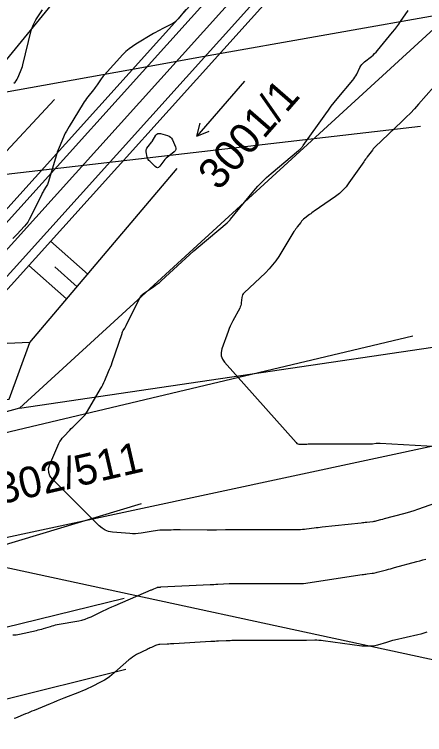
# Model space of a CAD drawing. Extents: x -534481 to -534256, y -1190577 to -1190138.
# Drawn here: x -534401.7 to -534390.37, y -1190524.99 to -1190505.1 of the extents above; entities that cross this region are included whole.
import ezdxf

# ---------------------------------------------------------------- set-up
doc = ezdxf.new("R2010")
doc.units = 0
for name, color, linetype in [('07_ELEKTRO', 7, 'Continuous'), ('30', 7, 'Continuous'), ('31', 7, 'Continuous'), ('_N_osa', 7, 'Continuous'), ('_N_text', 7, 'Continuous'), ('_tenka', 7, 'Continuous'), ('_velmi_tenka', 7, 'Continuous'), ('Hranice parcel', 7, 'Continuous'), ('Parcelní čísla', 7, 'Continuous'), ('Vnitřní kresba', 7, 'Continuous'), ('Značky kultur', 7, 'Continuous')]:
    doc.layers.add(name, color=color, linetype=linetype)

msp = doc.modelspace()

# ---------------------------------------------------------------- linework, layer by layer
at = {"layer": '07_ELEKTRO'}
msp.add_lwpolyline([(-534420.706, -1190521.11), (-534390.696, -1190513.981)], dxfattribs=at)
at = {"layer": '30'}
for points in [[(-534396.966, -1190504.966), (-534397.175, -1190505.224), (-534397.219, -1190505.273), (-534397.268, -1190505.317), (-534397.322, -1190505.355), (-534397.38, -1190505.388), (-534397.622, -1190505.506), (-534397.682, -1190505.536), (-534397.742, -1190505.567), (-534397.801, -1190505.6), (-534397.859, -1190505.634), (-534398.343, -1190505.924), (-534398.441, -1190505.987), (-534398.533, -1190506.057), (-534398.62, -1190506.133), (-534398.701, -1190506.216), (-534399.222, -1190506.783), (-534399.25, -1190506.814), (-534399.276, -1190506.846), (-534399.301, -1190506.88), (-534399.325, -1190506.914), (-534399.418, -1190507.053), (-534399.442, -1190507.088), (-534399.466, -1190507.122), (-534399.491, -1190507.155), (-534399.517, -1190507.188), (-534399.674, -1190507.383), (-534399.708, -1190507.427), (-534399.74, -1190507.472), (-534399.771, -1190507.518), (-534399.801, -1190507.565), (-534400.19, -1190508.201), (-534400.227, -1190508.262), (-534400.261, -1190508.325), (-534400.293, -1190508.388), (-534400.323, -1190508.453), (-534400.438, -1190508.714), (-534400.466, -1190508.78), (-534400.491, -1190508.846), (-534400.515, -1190508.913), (-534400.537, -1190508.981), (-534400.767, -1190509.743), (-534400.777, -1190509.772), (-534400.789, -1190509.801), (-534400.802, -1190509.829), (-534400.818, -1190509.856), (-534400.883, -1190509.963), (-534400.899, -1190509.99), (-534400.914, -1190510.017), (-534400.929, -1190510.045), (-534400.943, -1190510.073), (-534401.251, -1190510.705), (-534401.288, -1190510.773), (-534401.329, -1190510.838), (-534401.375, -1190510.899), (-534401.425, -1190510.957), (-534401.637, -1190511.183), (-534401.691, -1190511.239), (-534401.747, -1190511.292)], [(-534390.065, -1190518.606), (-534390.567, -1190518.78), (-534390.662, -1190518.811), (-534390.757, -1190518.841), (-534390.852, -1190518.869), (-534390.948, -1190518.895), (-534391.485, -1190519.038), (-534391.536, -1190519.051), (-534391.588, -1190519.065), (-534391.691, -1190519.093), (-534391.717, -1190519.099), (-534391.743, -1190519.105), (-534391.77, -1190519.11), (-534391.796, -1190519.114), (-534391.968, -1190519.135), (-534392.006, -1190519.14), (-534392.043, -1190519.144), (-534392.081, -1190519.149), (-534392.119, -1190519.153), (-534393.199, -1190519.268), (-534393.253, -1190519.274), (-534393.308, -1190519.281), (-534393.362, -1190519.287), (-534393.417, -1190519.294), (-534393.634, -1190519.323), (-534393.689, -1190519.329), (-534393.743, -1190519.334), (-534393.798, -1190519.336), (-534393.853, -1190519.337), (-534395.617, -1190519.337), (-534395.68, -1190519.337), (-534395.743, -1190519.338), (-534395.806, -1190519.339), (-534395.869, -1190519.34), (-534396.121, -1190519.345), (-534396.183, -1190519.346), (-534396.246, -1190519.347), (-534396.309, -1190519.347), (-534396.372, -1190519.347), (-534397.121, -1190519.343), (-534397.184, -1190519.342), (-534397.246, -1190519.343), (-534397.308, -1190519.343), (-534397.37, -1190519.345), (-534397.619, -1190519.35), (-534397.681, -1190519.352), (-534397.743, -1190519.357), (-534397.804, -1190519.364), (-534397.866, -1190519.374), (-534398.202, -1190519.431), (-534398.279, -1190519.441), (-534398.356, -1190519.447), (-534398.433, -1190519.447), (-534398.51, -1190519.443), (-534398.994, -1190519.399), (-534399.097, -1190519.382), (-534399.192, -1190519.347), (-534399.279, -1190519.296), (-534399.359, -1190519.229), (-534400.645, -1190517.942), (-534400.717, -1190517.85), (-534400.753, -1190517.752), (-534400.755, -1190517.646), (-534400.722, -1190517.535), (-534400.469, -1190516.954), (-534400.443, -1190516.901), (-534400.412, -1190516.85), (-534400.377, -1190516.803), (-534400.337, -1190516.758), (-534400.171, -1190516.586), (-534400.129, -1190516.543), (-534400.087, -1190516.501), (-534400.044, -1190516.459), (-534400.001, -1190516.417), (-534399.829, -1190516.25), (-534399.788, -1190516.207), (-534399.749, -1190516.162), (-534399.714, -1190516.114), (-534399.682, -1190516.063), (-534399.322, -1190515.448), (-534399.289, -1190515.39), (-534399.258, -1190515.332), (-534399.229, -1190515.272), (-534399.201, -1190515.211), (-534399.096, -1190514.967), (-534399.07, -1190514.905), (-534399.045, -1190514.844), (-534399.022, -1190514.781), (-534399, -1190514.718), (-534398.727, -1190513.914), (-534398.72, -1190513.894), (-534398.711, -1190513.875), (-534398.702, -1190513.857), (-534398.692, -1190513.838), (-534398.65, -1190513.766), (-534398.64, -1190513.748), (-534398.629, -1190513.73), (-534398.62, -1190513.711), (-534398.61, -1190513.693), (-534398.252, -1190512.965), (-534398.219, -1190512.908), (-534398.179, -1190512.856), (-534398.133, -1190512.811), (-534398.08, -1190512.771), (-534397.855, -1190512.624), (-534397.8, -1190512.586), (-534397.747, -1190512.546), (-534397.695, -1190512.504), (-534397.645, -1190512.46), (-534397.079, -1190511.936), (-534396.967, -1190511.834), (-534396.855, -1190511.733), (-534396.741, -1190511.634), (-534396.626, -1190511.536), (-534395.824, -1190510.859), (-534395.816, -1190510.852), (-534395.808, -1190510.844), (-534395.799, -1190510.836), (-534395.791, -1190510.829), (-534395.759, -1190510.797), (-534395.751, -1190510.789), (-534395.744, -1190510.78), (-534395.736, -1190510.772), (-534395.729, -1190510.763), (-534395.086, -1190509.98), (-534394.976, -1190509.851), (-534394.86, -1190509.728), (-534394.738, -1190509.61), (-534394.61, -1190509.499), (-534393.852, -1190508.864), (-534393.84, -1190508.854), (-534393.828, -1190508.844), (-534393.817, -1190508.833), (-534393.807, -1190508.822), (-534393.764, -1190508.777), (-534393.754, -1190508.765), (-534393.744, -1190508.753), (-534393.734, -1190508.741), (-534393.725, -1190508.729), (-534393.099, -1190507.849), (-534393.023, -1190507.745), (-534392.945, -1190507.642), (-534392.865, -1190507.54), (-534392.783, -1190507.44), (-534392.352, -1190506.923), (-534392.321, -1190506.883), (-534392.292, -1190506.841), (-534392.266, -1190506.798), (-534392.242, -1190506.753), (-534392.153, -1190506.57), (-534392.129, -1190506.526), (-534392.1, -1190506.486), (-534392.067, -1190506.449), (-534392.029, -1190506.416), (-534391.835, -1190506.263), (-534391.79, -1190506.226), (-534391.748, -1190506.186), (-534391.707, -1190506.145), (-534391.669, -1190506.101), (-534391.253, -1190505.595), (-534391.195, -1190505.523), (-534391.139, -1190505.45), (-534391.084, -1190505.375), (-534391.031, -1190505.3), (-534390.821, -1190504.996)], [(-534390.309, -1190522.164), (-534390.392, -1190522.192), (-534390.475, -1190522.216), (-534390.559, -1190522.237), (-534391.2, -1190522.386), (-534391.255, -1190522.399), (-534391.31, -1190522.414), (-534391.364, -1190522.429), (-534391.418, -1190522.446), (-534391.674, -1190522.526), (-534391.709, -1190522.535), (-534391.744, -1190522.542), (-534391.779, -1190522.547), (-534391.815, -1190522.549), (-534391.959, -1190522.554), (-534391.995, -1190522.555), (-534392.031, -1190522.554), (-534392.067, -1190522.551), (-534392.102, -1190522.547), (-534393.173, -1190522.403), (-534393.23, -1190522.396), (-534393.286, -1190522.392), (-534393.343, -1190522.39), (-534393.4, -1190522.39), (-534393.629, -1190522.396), (-534393.686, -1190522.397), (-534393.743, -1190522.398), (-534393.8, -1190522.398), (-534393.857, -1190522.399), (-534395.637, -1190522.399), (-534395.69, -1190522.399), (-534395.743, -1190522.4), (-534395.796, -1190522.402), (-534395.849, -1190522.404), (-534396.061, -1190522.415), (-534396.114, -1190522.418), (-534396.167, -1190522.421), (-534396.22, -1190522.424), (-534396.273, -1190522.427), (-534397.299, -1190522.484), (-534397.343, -1190522.487), (-534397.388, -1190522.489), (-534397.432, -1190522.492), (-534397.477, -1190522.494), (-534397.68, -1190522.505), (-534397.711, -1190522.508), (-534397.742, -1190522.514), (-534397.772, -1190522.522), (-534397.801, -1190522.534), (-534397.917, -1190522.586), (-534397.946, -1190522.599), (-534397.975, -1190522.613), (-534398.004, -1190522.626), (-534398.033, -1190522.641), (-534398.325, -1190522.786), (-534398.381, -1190522.817), (-534398.436, -1190522.851), (-534398.488, -1190522.889), (-534398.538, -1190522.93), (-534399.006, -1190523.342), (-534399.071, -1190523.396), (-534399.14, -1190523.445), (-534399.211, -1190523.49), (-534399.286, -1190523.53), (-534399.591, -1190523.681), (-534399.667, -1190523.718), (-534399.745, -1190523.753), (-534399.823, -1190523.786), (-534399.901, -1190523.818), (-534400.335, -1190523.989), (-534400.429, -1190524.027), (-534400.523, -1190524.065), (-534400.617, -1190524.103), (-534400.711, -1190524.142), (-534401.157, -1190524.327), (-534401.216, -1190524.351), (-534401.274, -1190524.375), (-534401.333, -1190524.399), (-534401.391, -1190524.423), (-534401.669, -1190524.536), (-534401.706, -1190524.549)]]:
    msp.add_lwpolyline(points, dxfattribs=at)
at = {"layer": '31'}
for points in [[(-534401.716, -1190507.007), (-534401.683, -1190506.973), (-534401.653, -1190506.937), (-534401.628, -1190506.897), (-534401.606, -1190506.855), (-534401.529, -1190506.679), (-534401.511, -1190506.635), (-534401.494, -1190506.59), (-534401.48, -1190506.545), (-534401.467, -1190506.499), (-534401.234, -1190505.552), (-534401.211, -1190505.474), (-534401.182, -1190505.399), (-534401.146, -1190505.326), (-534401.104, -1190505.256), (-534400.924, -1190504.982)], [(-534389.898, -1190506.863), (-534390.536, -1190507.586), (-534390.647, -1190507.708), (-534390.76, -1190507.828), (-534390.875, -1190507.945), (-534390.994, -1190508.06), (-534391.733, -1190508.758), (-534391.738, -1190508.763), (-534391.743, -1190508.768), (-534391.747, -1190508.773), (-534391.752, -1190508.778), (-534391.771, -1190508.801), (-534391.778, -1190508.809), (-534391.785, -1190508.818), (-534391.801, -1190508.84), (-534391.811, -1190508.853), (-534391.953, -1190509.04), (-534391.978, -1190509.072), (-534392.002, -1190509.105), (-534392.026, -1190509.138), (-534392.05, -1190509.172), (-534392.458, -1190509.76), (-534392.538, -1190509.865), (-534392.626, -1190509.961), (-534392.723, -1190510.05), (-534392.828, -1190510.13), (-534393.416, -1190510.538), (-534393.449, -1190510.561), (-534393.482, -1190510.585), (-534393.515, -1190510.609), (-534393.548, -1190510.634), (-534393.68, -1190510.735), (-534393.711, -1190510.76), (-534393.739, -1190510.787), (-534393.766, -1190510.816), (-534393.791, -1190510.847), (-534393.887, -1190510.973), (-534393.911, -1190511.005), (-534393.934, -1190511.038), (-534393.956, -1190511.071), (-534393.977, -1190511.104), (-534394.398, -1190511.786), (-534394.479, -1190511.907), (-534394.567, -1190512.023), (-534394.663, -1190512.133), (-534394.766, -1190512.237), (-534395.353, -1190512.792), (-534395.378, -1190512.82), (-534395.397, -1190512.85), (-534395.41, -1190512.884), (-534395.417, -1190512.92), (-534395.432, -1190513.072), (-534395.437, -1190513.11), (-534395.447, -1190513.146), (-534395.459, -1190513.181), (-534395.476, -1190513.215), (-534395.667, -1190513.568), (-534395.704, -1190513.638), (-534395.737, -1190513.71), (-534395.768, -1190513.783), (-534395.796, -1190513.858), (-534395.966, -1190514.337), (-534395.99, -1190514.439), (-534395.985, -1190514.536), (-534395.953, -1190514.627), (-534395.893, -1190514.713), (-534393.919, -1190516.93), (-534393.897, -1190516.951), (-534393.871, -1190516.965), (-534393.843, -1190516.974), (-534393.812, -1190516.975), (-534393.684, -1190516.97), (-534393.652, -1190516.969), (-534393.62, -1190516.969), (-534393.588, -1190516.968), (-534393.555, -1190516.968), (-534391.922, -1190516.968), (-534391.894, -1190516.967), (-534391.867, -1190516.966), (-534391.839, -1190516.964), (-534391.812, -1190516.961), (-534391.702, -1190516.947), (-534391.675, -1190516.944), (-534391.647, -1190516.943), (-534391.62, -1190516.942), (-534391.592, -1190516.943), (-534389.984, -1190517.034)], [(-534401.742, -1190522.239), (-534401.649, -1190522.237), (-534401.555, -1190522.222), (-534401.089, -1190522.116), (-534401.041, -1190522.104), (-534400.993, -1190522.092), (-534400.945, -1190522.078), (-534400.897, -1190522.064), (-534400.707, -1190522.005), (-534400.659, -1190521.991), (-534400.611, -1190521.978), (-534400.563, -1190521.967), (-534400.514, -1190521.957), (-534399.922, -1190521.849), (-534399.833, -1190521.829), (-534399.747, -1190521.804), (-534399.662, -1190521.773), (-534399.579, -1190521.737), (-534399.251, -1190521.579), (-534399.169, -1190521.54), (-534399.087, -1190521.502), (-534399.004, -1190521.465), (-534398.92, -1190521.429), (-534397.919, -1190521), (-534397.901, -1190520.993), (-534397.884, -1190520.985), (-534397.866, -1190520.977), (-534397.849, -1190520.969), (-534397.76, -1190520.93), (-534397.751, -1190520.926), (-534397.743, -1190520.924), (-534397.734, -1190520.922), (-534397.725, -1190520.921), (-534397.66, -1190520.918), (-534397.651, -1190520.917), (-534396.295, -1190520.85), (-534396.242, -1190520.847), (-534396.189, -1190520.845), (-534396.136, -1190520.842), (-534396.082, -1190520.839), (-534395.769, -1190520.824), (-534395.758, -1190520.824), (-534395.738, -1190520.824), (-534393.749, -1190520.824), (-534393.74, -1190520.823), (-534393.716, -1190520.82), (-534393.713, -1190520.82), (-534392.094, -1190520.574), (-534392.059, -1190520.569), (-534392.024, -1190520.564), (-534391.989, -1190520.56), (-534391.954, -1190520.555), (-534391.813, -1190520.537), (-534391.778, -1190520.532), (-534391.744, -1190520.526), (-534391.709, -1190520.519), (-534391.675, -1190520.51), (-534391.419, -1190520.442), (-534391.365, -1190520.427), (-534391.311, -1190520.412), (-534391.257, -1190520.398), (-534391.203, -1190520.383), (-534390.585, -1190520.216), (-534390.501, -1190520.193), (-534390.417, -1190520.171), (-534390.333, -1190520.148)]]:
    msp.add_lwpolyline(points, dxfattribs=at)
msp.add_lwpolyline([(-534397.715, -1190509.328), (-534397.746, -1190509.339), (-534397.777, -1190509.333), (-534397.811, -1190509.309), (-534397.963, -1190509.162), (-534397.986, -1190509.137), (-534398.004, -1190509.109), (-534398.018, -1190509.079), (-534398.028, -1190509.047), (-534398.06, -1190508.902), (-534398.064, -1190508.874), (-534398.061, -1190508.847), (-534398.052, -1190508.822), (-534398.037, -1190508.798), (-534397.964, -1190508.706), (-534397.946, -1190508.683), (-534397.929, -1190508.659), (-534397.912, -1190508.635), (-534397.896, -1190508.61), (-534397.789, -1190508.444), (-534397.764, -1190508.414), (-534397.734, -1190508.396), (-534397.7, -1190508.39), (-534397.661, -1190508.396), (-534397.468, -1190508.452), (-534397.426, -1190508.469), (-534397.39, -1190508.493), (-534397.36, -1190508.525), (-534397.337, -1190508.565), (-534397.25, -1190508.758), (-534397.238, -1190508.799), (-534397.24, -1190508.837), (-534397.256, -1190508.871), (-534397.287, -1190508.902), (-534397.438, -1190509.017), (-534397.475, -1190509.047), (-534397.509, -1190509.079), (-534397.541, -1190509.113), (-534397.571, -1190509.149), (-534397.686, -1190509.3)], close=True, dxfattribs=at)
at = {"layer": '_N_osa'}
msp.add_line((-534422.24, -1190529.075), (-534398.624, -1190523.185), dxfattribs=at)
msp.add_lwpolyline([(-534408.105, -1190518.46), (-534393.616, -1190502.389), (-534391.346, -1190496.962), (-534392.763, -1190488.017), (-534396.655, -1190477.752), (-534402.513, -1190464.283), (-534404.757, -1190456.741), (-534408.311, -1190433.088), (-534409.248, -1190427.879), (-534409.316, -1190416.054), (-534409.076, -1190409.418), (-534409.868, -1190391.439)], dxfattribs=at)
at = {"layer": '_N_text'}
msp.add_line((-534405.885, -1190519.52), (-534380.58, -1190524.995), dxfattribs=at)
at = {"layer": '_tenka'}
for p, q in [((-534407.09, -1190514.42), (-534400.591, -1190507.452)), ((-534416.715, -1190511.238), (-534390.485, -1190508.189)), ((-534401.27, -1190514.17), (-534397.206, -1190509.36)), ((-534398.2, -1190518.62), (-534407.09, -1190521.3))]:
    msp.add_line(p, q, dxfattribs=at)
for points in [[(-534405.407, -1190514.348), (-534394.258, -1190501.982), (-534392.12, -1190496.869), (-534393.492, -1190488.211), (-534397.35, -1190478.035), (-534403.219, -1190464.54), (-534405.491, -1190456.905), (-534409.051, -1190433.21), (-534409.998, -1190427.948), (-534410.066, -1190416.042), (-534409.827, -1190409.421), (-534410.645, -1190390.84)], [(-534405.057, -1190514.333), (-534394.044, -1190502.118), (-534391.862, -1190496.9), (-534393.249, -1190488.146), (-534397.118, -1190477.94), (-534402.983, -1190464.455), (-534405.247, -1190456.85), (-534408.804, -1190433.17), (-534409.748, -1190427.925), (-534409.816, -1190416.046), (-534409.577, -1190409.42), (-534410.397, -1190390.795)], [(-534403.656, -1190514.273), (-534393.187, -1190502.661), (-534390.83, -1190497.024), (-534392.278, -1190487.888), (-534396.191, -1190477.563), (-534402.042, -1190464.111), (-534404.268, -1190456.632), (-534407.818, -1190433.007), (-534408.749, -1190427.833), (-534408.816, -1190416.061), (-534408.576, -1190409.416), (-534409.363, -1190391.537)], [(-534403.306, -1190514.257), (-534392.973, -1190502.796), (-534390.572, -1190497.055), (-534392.035, -1190487.824), (-534395.96, -1190477.469), (-534401.807, -1190464.025), (-534404.023, -1190456.578), (-534407.571, -1190432.966), (-534408.499, -1190427.81), (-534408.566, -1190416.065), (-534408.326, -1190409.415), (-534409.111, -1190391.586)], [(-534422.71, -1190527.13), (-534410.3, -1190523.97), (-534409.53, -1190523.89), (-534398.67, -1190521.23)]]:
    msp.add_lwpolyline(points, dxfattribs=at)
at = {"layer": '_velmi_tenka'}
for p, q in [((-534399.665, -1190512.289), (-534400.7, -1190511.367)), ((-534400.264, -1190512.961), (-534401.303, -1190512.035)), ((-534399.965, -1190512.625), (-534400.582, -1190512.075))]:
    msp.add_line(p, q, dxfattribs=at)
at = {"layer": 'Hranice parcel'}
for p, q in [((-534402.95, -1190507.61), (-534395.53, -1190498.55)), ((-534389.63, -1190505.06), (-534401.56, -1190515.98)), ((-534401.56, -1190515.98), (-534378.386, -1190512.549))]:
    msp.add_line(p, q, dxfattribs=at)
for points in [[(-534389.63, -1190505.06), (-534396.5, -1190506.28), (-534398.08, -1190506.56), (-534402.44, -1190507.34), (-534402.95, -1190507.61)], [(-534378.833, -1190515.085), (-534383.27, -1190515.56), (-534409.16, -1190521.11), (-534410.57, -1190521.41), (-534422.34, -1190523.93)], [(-534401.56, -1190515.98), (-534406.2, -1190517.26), (-534407.55, -1190517.63), (-534412.19, -1190518.9)]]:
    msp.add_lwpolyline(points, dxfattribs=at)
at = {"layer": 'Vnitřní kresba'}
msp.add_lwpolyline([(-534407.09, -1190514.42), (-534407.09, -1190514.42), (-534407.95, -1190515.91), (-534401.84, -1190515.73), (-534401.27, -1190514.17), (-534407.09, -1190514.42)], dxfattribs=at)
at = {"layer": 'Značky kultur'}
for p, q in [((-534395.341, -1190506.951), (-534396.66, -1190508.468)), ((-534396.66, -1190508.468), (-534396.572, -1190508.11)), ((-534396.66, -1190508.468), (-534396.318, -1190508.331))]:
    msp.add_line(p, q, dxfattribs=at)

# ---------------------------------------------------------------- texts
at = {"layer": 'Parcelní čísla'}
for s, rotation, p in [('3001/1', 49, (-534396.057, -1190509.998)), ('2302/511', 13, (-534402.712, -1190518.785))]:
    msp.add_text(s, height=0.85, rotation=rotation, dxfattribs=at).set_placement(p)

doc.saveas('drawing.dxf')
